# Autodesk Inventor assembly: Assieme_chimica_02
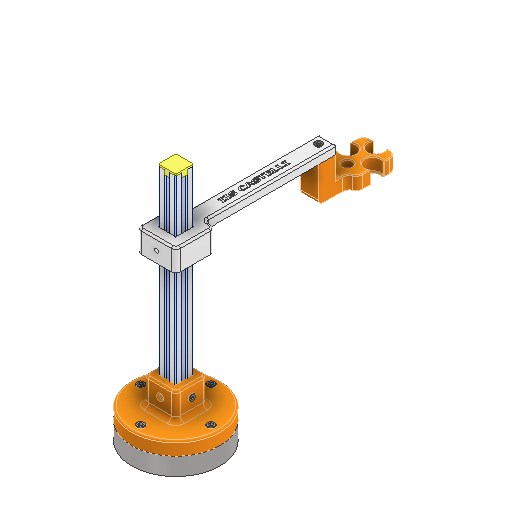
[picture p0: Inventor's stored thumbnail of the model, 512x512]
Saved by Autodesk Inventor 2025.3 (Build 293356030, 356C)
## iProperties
Created: 2025-09
Part Number: Assieme_chimica_02
Document SubType Name: Assembly
Designer: Ryzen5700u
Author: Ryzen5700u
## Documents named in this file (14)
- C:\Users\R5800u\Downloads\chimica\Assieme_chimica_02.iam
- C:\Users\R5800u\Downloads\chimica\tslot-20x20-3_MIR1.ipt
- C:\Users\R5800u\Downloads\chimica\base_ferro.ipt
- C:\Users\R5800u\Downloads\chimica\braccio.ipt
- C:\Users\R5800u\Downloads\chimica\tappo_2020.ipt
- C:\Users\R5800u\Downloads\chimica\vite_blocco.ipt
- C:\Users\R5800u\Downloads\chimica\porta_sensore.ipt
- C:\Users\R5800u\Documents\Inventor\Content Center Files\R2025\it-IT\AS 1420\AS 1420 - 1973 - M5 x 20.ipt
- C:\Users\R5800u\Documents\Inventor\Content Center Files\R2025\it-IT\AS 1112 (2)\AS 1112 - M4  Tipo 5.ipt
- C:\Users\R5800u\Documents\Inventor\Content Center Files\R2025\it-IT\AS 1420\AS 1420 - 1973 - M4 x 8.ipt
- C:\Users\R5800u\Documents\Inventor\Content Center Files\R2025\it-IT\AS 1420\AS 1420 - 1973 - M5 x 35.ipt
- C:\Users\R5800u\Documents\Inventor\Content Center Files\R2025\it-IT\AS 1420\AS 1420 - 1973 - M4 x 30.ipt
- C:\Users\R5800u\Downloads\chimica\Slider T-Nut for 2020 - M4.ipt
- C:\Users\R5800u\Downloads\chimica\base_petg2.ipt
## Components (19 placed, 13 different names)
1. tslot-20x20-3_MIR1:1
2. base_petg2:1
3. base_ferro:1 — Allineato:6
4. braccio:1
5. tappo_2020:1 — Allineato:8
6. vite_blocco:1 — Allineato:9, Coincidente:22
7. porta_sensore:1 — Allineato:10, Coincidente:23, Angolo:2, Rotazionale:3
8. AS 1420 - Metrico M5 x 20:1 — Coincidente:6
9. AS 1420 - Metrico M5 x 20:2 — Coincidente:8
10. AS 1420 - Metrico M5 x 20:3 — Coincidente:10
11. AS 1420 - Metrico M5 x 20:4 — Coincidente:12
12. AS 1112 (2) - Metrico M4  Tipo 5:1
13. AS 1112 (2) - Metrico M4  Tipo 5:2
14. AS 1420 - Metrico M5 x 35:1 — Rotazionale:1
15. AS 1420 - Metrico M4 x 8:4 — Rotazionale:4
16. AS 1112 (2) - Metrico M4  Tipo 5:3 — Rotazionale:3
17. AS 1420 - Metrico M4 x 30:1 — Rotazionale:2, Coincidente:23
18. Slider T-Nut for 2020 - M4:1 — Angolo:1, Coincidente:19, Coincidente:20, Coincidente:24
19. AS 1420 - Metrico M4 x 8:5 — Rotazionale:5
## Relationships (20: Mate 9, RevoluteJoint 5, Flush 4, Angle 2)
- Allineato:6 [Flush]: base_ferro:1
- Allineato:8 [Flush]: tappo_2020:1
- Allineato:9 [Flush]: vite_blocco:1
- Allineato:10 [Flush]: porta_sensore:1
- Coincidente:6 [Mate]: AS 1420 - Metrico M5 x 20:1
- Coincidente:8 [Mate]: AS 1420 - Metrico M5 x 20:2
- Coincidente:10 [Mate]: AS 1420 - Metrico M5 x 20:3
- Coincidente:12 [Mate]: AS 1420 - Metrico M5 x 20:4
- Rotazionale:1 [RevoluteJoint]: AS 1420 - Metrico M5 x 35:1
- Rotazionale:2 [RevoluteJoint]: AS 1420 - Metrico M4 x 30:1
- Angolo:1 [Angle]: Slider T-Nut for 2020 - M4:1
- Coincidente:19 [Mate]: Slider T-Nut for 2020 - M4:1
- Coincidente:20 [Mate]: Slider T-Nut for 2020 - M4:1
- Coincidente:22 [Mate]: vite_blocco:1
- Coincidente:23 [Mate]: porta_sensore:1 ↔ AS 1420 - Metrico M4 x 30:1
- Angolo:2 [Angle]: porta_sensore:1
- Rotazionale:3 [RevoluteJoint]: porta_sensore:1 ↔ AS 1112 (2) - Metrico M4  Tipo 5:3
- Coincidente:24 [Mate]: Slider T-Nut for 2020 - M4:1
- Rotazionale:4 [RevoluteJoint]: AS 1420 - Metrico M4 x 8:4
- Rotazionale:5 [RevoluteJoint]: AS 1420 - Metrico M4 x 8:5
